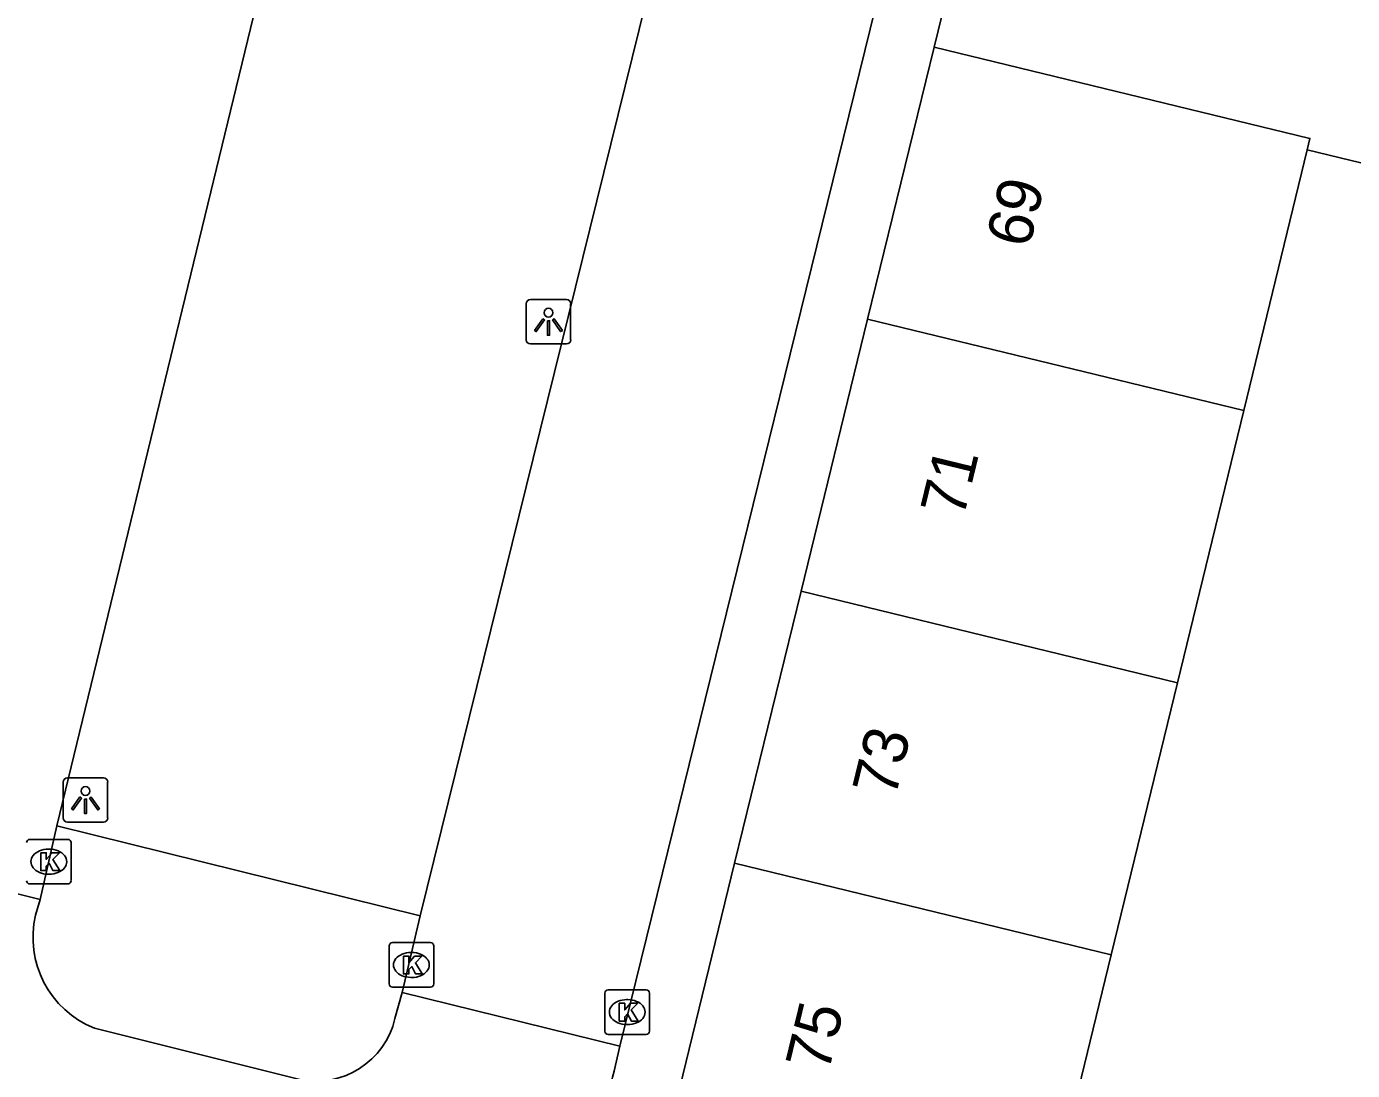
# Model space of a CAD drawing. Extents: x 162812 to 163818, y 381639 to 382470.
# Drawn here: x 163318.59 to 163348.31, y 382334.65 to 382358.06 of the extents above; entities that cross this region are included whole.
import ezdxf

# ---------------------------------------------------------------- set-up
doc = ezdxf.new("R2010")
doc.units = 0
for name, color, linetype in [('IMGEO_Groenvoorziening', 7, 'Continuous'), ('IMGEO_Kolk', 7, 'Continuous'), ('IMGEO_Lichtpunt', 7, 'Continuous'), ('IMGEO_Pand', 7, 'Continuous'), ('IMGEO_Pand_nummerreeks', 7, 'Continuous'), ('IMGEO_Rijbaan_lokaal_open', 7, 'Continuous')]:
    doc.layers.add(name, color=color, linetype=linetype)

msp = doc.modelspace()

# ---------------------------------------------------------------- linework, layer by layer
at = {"layer": 'IMGEO_Groenvoorziening'}
msp.add_lwpolyline([(163319.271, 382340.139), (163327.408, 382338.123)], dxfattribs=at)
at = {"layer": 'IMGEO_Kolk'}
for p, q in [((163318.664, 382339.835), (163319.516, 382339.835)), ((163319.077, 382339.615), (163319.102, 382339.615)), ((163319.59, 382339.761), (163319.59, 382338.909)), ((163319.1, 382339.055), (163319.075, 382339.055)), ((163319.516, 382338.835), (163318.664, 382338.835)), ((163326.714, 382336.593), (163326.714, 382337.445)), ((163326.789, 382337.519), (163327.641, 382337.519)), ((163327.715, 382337.445), (163327.715, 382336.593)), ((163327.202, 382337.299), (163327.227, 382337.299)), ((163327.225, 382336.739), (163327.2, 382336.739)), ((163327.641, 382336.519), (163326.789, 382336.519)), ((163331.551, 382335.536), (163331.551, 382336.388)), ((163331.626, 382336.462), (163332.478, 382336.462)), ((163332.039, 382336.242), (163332.064, 382336.242)), ((163332.552, 382336.388), (163332.552, 382335.536)), ((163332.062, 382335.682), (163332.037, 382335.682)), ((163332.478, 382335.462), (163331.626, 382335.462))]:
    msp.add_line(p, q, dxfattribs=at)
for points in [[(163318.664, 382339.835), (163319.516, 382339.835)], [(163318.91, 382339.535), (163319.033, 382339.535), (163319.033, 382339.384), (163319.163, 382339.535), (163319.327, 382339.535), (163319.181, 382339.384), (163319.334, 382339.135), (163319.182, 382339.135), (163319.097, 382339.299), (163319.033, 382339.232), (163319.033, 382339.135), (163318.91, 382339.135), (163318.91, 382339.535)], [(163319.59, 382339.761), (163319.59, 382338.909)], [(163319.516, 382338.835), (163318.664, 382338.835)], [(163326.714, 382336.593), (163326.714, 382337.445)], [(163326.789, 382337.519), (163327.641, 382337.519)], [(163327.715, 382337.445), (163327.715, 382336.593)], [(163327.035, 382337.219), (163327.158, 382337.219), (163327.158, 382337.068), (163327.288, 382337.219), (163327.452, 382337.219), (163327.306, 382337.068), (163327.459, 382336.819), (163327.307, 382336.819), (163327.222, 382336.983), (163327.158, 382336.916), (163327.158, 382336.819), (163327.035, 382336.819), (163327.035, 382337.219)], [(163327.641, 382336.519), (163326.789, 382336.519)], [(163331.551, 382335.536), (163331.551, 382336.388)], [(163331.626, 382336.462), (163332.478, 382336.462)], [(163332.552, 382336.388), (163332.552, 382335.536)], [(163331.872, 382336.162), (163331.995, 382336.162), (163331.995, 382336.011), (163332.125, 382336.162), (163332.289, 382336.162), (163332.143, 382336.011), (163332.296, 382335.762), (163332.144, 382335.762), (163332.059, 382335.926), (163331.995, 382335.859), (163331.995, 382335.762), (163331.872, 382335.762), (163331.872, 382336.162)], [(163332.478, 382335.462), (163331.626, 382335.462)]]:
    msp.add_lwpolyline(points, dxfattribs=at)
for centre, start, end in [((163318.666, 382339.759), 91.552, 178.448), ((163318.666, 382339.759), 91.552, 178.448), ((163319.514, 382339.759), 1.552, 88.448), ((163319.514, 382339.759), 1.552, 88.448), ((163318.666, 382338.911), 181.552, 268.448), ((163318.666, 382338.911), 181.552, 268.448), ((163319.514, 382338.911), 271.552, 358.448), ((163319.514, 382338.911), 271.552, 358.448), ((163326.791, 382337.443), 91.552, 178.448), ((163326.791, 382337.443), 91.552, 178.448), ((163327.639, 382337.443), 1.552, 88.448), ((163327.639, 382337.443), 1.552, 88.448), ((163326.791, 382336.595), 181.552, 268.448), ((163326.791, 382336.595), 181.552, 268.448), ((163327.639, 382336.595), 271.552, 358.448), ((163327.639, 382336.595), 271.552, 358.448), ((163331.628, 382336.386), 91.552, 178.448), ((163331.628, 382336.386), 91.552, 178.448), ((163332.476, 382336.386), 1.552, 88.448), ((163332.476, 382336.386), 1.552, 88.448), ((163331.628, 382335.538), 181.552, 268.448), ((163331.628, 382335.538), 181.552, 268.448), ((163332.476, 382335.538), 271.552, 358.448), ((163332.476, 382335.538), 271.552, 358.448)]:
    msp.add_arc(centre, 0.0765, start, end, dxfattribs=at)
for centre, major_axis, ratio, start_param, end_param in [((163319.076, 382339.335), (-0.387, 0.002), 0.722429, 4.712389, 7.853982), ((163319.101, 382339.335), (-0.39, 0.002), 0.717154, 1.570796, 4.712389), ((163327.201, 382337.019), (-0.387, 0.002), 0.722429, 4.712389, 7.853982), ((163327.226, 382337.019), (-0.39, 0.002), 0.717154, 1.570796, 4.712389), ((163332.038, 382335.962), (-0.387, 0.002), 0.722429, 4.712389, 7.853982), ((163332.063, 382335.962), (-0.39, 0.002), 0.717154, 1.570796, 4.712389)]:
    msp.add_ellipse(centre, major_axis=major_axis, ratio=ratio, start_param=start_param, end_param=end_param, dxfattribs=at)
at = {"layer": 'IMGEO_Lichtpunt'}
for p, q in [((163329.788, 382351.845), (163329.788, 382351.038)), ((163329.788, 382351.845), (163329.788, 382351.038)), ((163330.69, 382351.94), (163329.882, 382351.94)), ((163330.69, 382351.94), (163329.882, 382351.94)), ((163330.784, 382351.038), (163330.784, 382351.845)), ((163330.784, 382351.038), (163330.784, 382351.845)), ((163329.882, 382350.944), (163330.69, 382350.944)), ((163329.882, 382350.944), (163330.69, 382350.944)), ((163319.412, 382341.121), (163319.412, 382340.314)), ((163319.412, 382341.121), (163319.412, 382340.314)), ((163320.314, 382341.216), (163319.506, 382341.216)), ((163320.314, 382341.216), (163319.506, 382341.216)), ((163320.408, 382340.314), (163320.408, 382341.121)), ((163320.408, 382340.314), (163320.408, 382341.121)), ((163319.506, 382340.22), (163320.314, 382340.22)), ((163319.506, 382340.22), (163320.314, 382340.22))]:
    msp.add_line(p, q, dxfattribs=at)
for points in [[(163330.162, 382351.509), (163330.201, 382351.481), (163330.013, 382351.219), (163329.975, 382351.246), (163330.162, 382351.509)], [(163330.264, 382351.461), (163330.311, 382351.461), (163330.311, 382351.139), (163330.264, 382351.139), (163330.264, 382351.461)], [(163330.374, 382351.481), (163330.412, 382351.508), (163330.599, 382351.246), (163330.56, 382351.218), (163330.374, 382351.481)], [(163319.786, 382340.785), (163319.825, 382340.757), (163319.637, 382340.495), (163319.599, 382340.522), (163319.786, 382340.785)], [(163319.888, 382340.737), (163319.935, 382340.737), (163319.935, 382340.415), (163319.888, 382340.415), (163319.888, 382340.737)], [(163319.998, 382340.757), (163320.036, 382340.784), (163320.223, 382340.522), (163320.184, 382340.494), (163319.998, 382340.757)]]:
    msp.add_lwpolyline(points, dxfattribs=at)
for centre in [(163330.287, 382351.643), (163319.911, 382340.919)]:
    msp.add_circle(centre, 0.0994, dxfattribs=at)
for centre, start, end in [((163329.882, 382351.845), 90, 180), ((163329.882, 382351.845), 90, 180), ((163330.69, 382351.845), 0, 90), ((163330.69, 382351.845), 0, 90), ((163329.882, 382351.038), 180, 270), ((163329.882, 382351.038), 180, 270), ((163330.69, 382351.038), 270, 0), ((163330.69, 382351.038), 270, 360), ((163319.506, 382341.121), 90, 180), ((163319.506, 382341.121), 90, 180), ((163320.314, 382341.121), 0, 90), ((163320.314, 382341.121), 0, 90), ((163319.506, 382340.314), 180, 270), ((163319.506, 382340.314), 180, 270), ((163320.314, 382340.314), 270, 0), ((163320.314, 382340.314), 270, 360)]:
    msp.add_arc(centre, 0.0946, start, end, dxfattribs=at)
at = {"layer": 'IMGEO_Pand'}
for points in [[(163343.643, 382363.071), (163343.568, 382362.76), (163341.974, 382363.143), (163340.379, 382363.526), (163338.931, 382357.599)], [(163351.873, 382360.614), (163350.406, 382354.539), (163347.291, 382355.298)], [(163338.931, 382357.599), (163337.44, 382351.5)], [(163347.291, 382355.298), (163347.352, 382355.55), (163338.931, 382357.599)], [(163347.291, 382355.298), (163345.867, 382349.449)], [(163335.949, 382345.4), (163337.44, 382351.5)], [(163337.44, 382351.5), (163345.867, 382349.449)], [(163345.867, 382349.449), (163344.383, 382343.348)], [(163334.458, 382339.301), (163335.949, 382345.4)], [(163344.383, 382343.348), (163335.949, 382345.4)], [(163344.383, 382343.348), (163342.898, 382337.247)], [(163334.458, 382339.301), (163332.861, 382332.769)], [(163342.898, 382337.247), (163334.458, 382339.301)], [(163342.898, 382337.247), (163342.561, 382335.862), (163341.378, 382331.002), (163341.308, 382330.714), (163337.088, 382331.753), (163332.861, 382332.769)]]:
    msp.add_lwpolyline(points, dxfattribs=at)
at = {"layer": 'IMGEO_Rijbaan_lokaal_open'}
for points in [[(163338.929, 382363.835), (163331.884, 382335.197)], [(163324.756, 382362.762), (163319.271, 382340.139)], [(163327.408, 382338.123), (163332.955, 382360.57)], [(163318.898, 382338.486), (163319.271, 382340.139)], [(163318.898, 382338.486), (163314.048, 382339.705)], [(163318.794, 382338.137), (163318.898, 382338.486)], [(163327.408, 382338.123), (163327.006, 382336.402)], [(163327.006, 382336.402), (163326.846, 382335.815)], [(163331.884, 382335.197), (163327.006, 382336.402)], [(163324.712, 382334.45), (163320.112, 382335.603)], [(163331.884, 382335.197), (163331.791, 382334.773)]]:
    msp.add_lwpolyline(points, dxfattribs=at)
for centre, radius, start, end in [((163320.913, 382337.63), 2.179, 166.5373, 248.423), ((163325.074, 382336.235), 1.821, 258.5351, 346.6745), ((163338.298, 382332.98), 6.749, 164.5921, 201.8206)]:
    msp.add_arc(centre, radius, start, end, dxfattribs=at)

# ---------------------------------------------------------------- texts
at = {"layer": 'IMGEO_Pand_nummerreeks'}
for s, rotation, p in [('69', 76.3237, (163341.056, 382353.064)), ('71', 76.322, (163339.583, 382347.015)), ('73', 76.322, (163338.057, 382340.745)), ('75', 76.3237, (163336.559, 382334.586))]:
    msp.add_text(s, height=1, rotation=rotation, dxfattribs=at).set_placement(p)

doc.saveas('drawing.dxf')
